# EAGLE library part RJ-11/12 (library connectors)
6 Pin RJ-12 Connector Digikey Part Number: A9031-ND
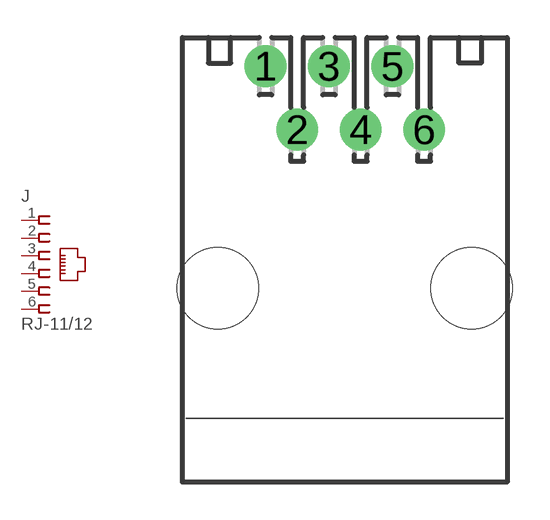
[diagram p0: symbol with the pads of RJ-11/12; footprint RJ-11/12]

Designator prefix J

## RJ-11/12TH  [RJ-11/12]
1  1  pas
2  2  pas
3  3  pas
4  4  pas
5  5  pas
6  6  pas

## Footprint RJ-11/12 (pad centres in mm)
Modular Jack without Panel Stops
drill 0.889 pad 1.676 round: 1 -3.175,7.747; 2 -1.905,5.207; 3 -0.635,7.747; 4 0.635,5.207; 5 1.905,7.747; 6 3.175,5.207
hole 3.251 at -5.08,-1.143
hole 3.251 at 5.08,-1.143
